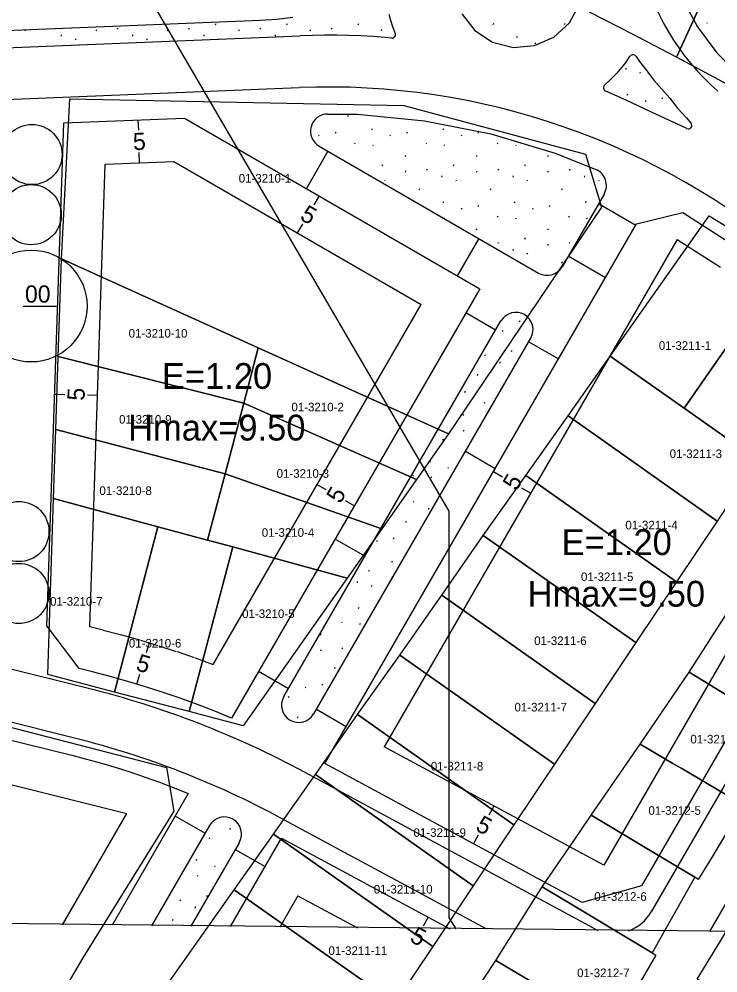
# Model space of a CAD drawing. Extents: x 419396 to 421519, y 4453567 to 4456767.
# Drawn here: x 420843 to 420924.3, y 4454304 to 4454414.9 of the extents above; entities that cross this region are included whole.
import ezdxf

# ---------------------------------------------------------------- set-up
doc = ezdxf.new("R2010")
doc.units = 0
for name, color, linetype in [('0_KADASTRO', 7, 'Continuous'), ('Level 20', 7, 'Continuous'), ('Level 21', 7, 'Continuous'), ('Level 28', 7, 'Continuous'), ('Level 29', 7, 'Continuous'), ('Level 30', 7, 'Continuous'), ('Level 41', 7, 'Continuous'), ('Level 55', 7, 'Continuous'), ('Level 58', 7, 'Continuous'), ('Level 62', 7, 'Continuous'), ('Y_Lejant', 7, 'Continuous')]:
    doc.layers.add(name, color=color, linetype=linetype)

msp = doc.modelspace()

# ---------------------------------------------------------------- linework, layer by layer
at = {"layer": '0_KADASTRO'}
for points in [[(420919.48, 4454410.46), (420927.96, 4454429.01), (420933.84, 4454443.01), (420940.66, 4454439.98), (420932.4, 4454411.65), (420927.17, 4454406.36)], [(420847.97, 4454387.04), (420848.94, 4454405.63), (420887.76, 4454404.85), (420908.91, 4454399.19), (420910.74, 4454393.05), (420892.97, 4454366.7), (420870.84, 4454376.71)], [(420911.76, 4454375.72), (420923.26, 4454392.04), (420932.15, 4454386.63), (420920.36, 4454369.67)], [(420847.59, 4454375.69), (420847.97, 4454387.04), (420870.84, 4454376.71), (420869.17, 4454370.28)], [(420920.36, 4454369.67), (420932.15, 4454386.63), (420932.45, 4454386.45), (420939.89, 4454379.98), (420928.94, 4454363.63)], [(420869.17, 4454370.28), (420870.84, 4454376.71), (420892.97, 4454366.7), (420889.23, 4454361.38)], [(420847.31, 4454367.19), (420847.59, 4454375.69), (420869.17, 4454370.28), (420866.98, 4454362.06)], [(420906.87, 4454368.79), (420911.76, 4454375.72), (420920.36, 4454369.67), (420928.94, 4454363.63), (420924.22, 4454356.56)], [(420866.98, 4454362.06), (420869.17, 4454370.28), (420889.23, 4454361.38), (420885.21, 4454355.65)], [(420901.97, 4454361.84), (420906.87, 4454368.79), (420924.22, 4454356.56), (420919.49, 4454349.5)], [(420847.05, 4454359.2), (420847.31, 4454367.19), (420866.98, 4454362.06), (420864.93, 4454354.34), (420859.18, 4454355.9)], [(420864.93, 4454354.34), (420866.98, 4454362.06), (420885.21, 4454355.65), (420881.19, 4454349.93), (420867.88, 4454353.55)], [(420896.98, 4454354.89), (420901.97, 4454361.84), (420919.49, 4454349.5), (420914.76, 4454342.43)], [(420846.37, 4454338.71), (420847.05, 4454359.2), (420859.18, 4454355.9), (420854.11, 4454336.69)], [(420854.11, 4454336.69), (420859.18, 4454355.9), (420864.93, 4454354.34), (420867.88, 4454353.55), (420862.82, 4454334.41)], [(420892.18, 4454347.94), (420896.98, 4454354.89), (420914.76, 4454342.43), (420910.03, 4454335.37)], [(420920.97, 4454338.99), (420925.86, 4454346.65), (420927.58, 4454349.24), (420931.35, 4454354.92), (420934.95, 4454352.64), (420941.51, 4454348.47), (420936.65, 4454339.79), (420932.18, 4454332.07), (420926.57, 4454335.53), (420923.87, 4454337.2), (420923.23, 4454337.6)], [(420862.82, 4454334.41), (420867.88, 4454353.55), (420881.19, 4454349.93), (420869.1, 4454332.77)], [(420760.42, 4454295.25), (420766.53, 4454352.09), (420860.16, 4454327.91), (420861.03, 4454322.83), (420850.45, 4454305.8), (420831.03, 4454272.79)], [(420887.29, 4454340.99), (420892.18, 4454347.94), (420910.03, 4454335.37), (420905.3, 4454328.31)], [(420882.4, 4454334.06), (420887.29, 4454340.99), (420905.3, 4454328.31), (420900.58, 4454321.24)], [(420915.27, 4454330.63), (420920.97, 4454338.99), (420923.23, 4454337.6), (420923.87, 4454337.2), (420926.57, 4454335.53), (420932.18, 4454332.07), (420927.24, 4454323.56), (420920.1, 4454327.78), (420919.06, 4454328.39)], [(420877.49, 4454327.1), (420882.4, 4454334.06), (420900.58, 4454321.24), (420895.85, 4454314.17)], [(420909.56, 4454322.37), (420915.27, 4454330.63), (420919.06, 4454328.39), (420920.1, 4454327.78), (420927.24, 4454323.56), (420923.49, 4454317.35), (420922.01, 4454314.91), (420921.61, 4454315.15), (420916.01, 4454318.5), (420913.52, 4454320), (420911.58, 4454321.16)], [(420872.6, 4454320.16), (420877.49, 4454327.1), (420895.85, 4454314.17), (420891.13, 4454307.11)], [(420903.86, 4454314.03), (420905.22, 4454316.02), (420908.26, 4454320.46), (420909.56, 4454322.37), (420911.58, 4454321.16), (420913.52, 4454320), (420916.01, 4454318.5), (420921.61, 4454315.15), (420916.66, 4454306.36), (420906.26, 4454312.6)], [(420868.04, 4454313.69), (420872.6, 4454320.16), (420891.13, 4454307.11), (420886.72, 4454300.53)], [(420858.1, 4454299.58), (420868.04, 4454313.69), (420886.72, 4454300.53), (420878.49, 4454288.23)], [(420898.46, 4454305.5), (420903.86, 4454314.03), (420906.26, 4454312.6), (420916.66, 4454306.36), (420917.06, 4454306.11), (420912.04, 4454297.41)], [(420921.9, 4454303.31), (420924.64, 4454307.82), (420926.86, 4454311.47), (420927.5, 4454311.11), (420930.28, 4454309.59), (420939.64, 4454304.45), (420935.53, 4454297.94), (420934.37, 4454296.12), (420930.15, 4454298.55)], [(420887.01, 4454288.07), (420898.46, 4454305.5), (420912.04, 4454297.41), (420906.85, 4454288.65), (420901.63, 4454279.83), (420897.9, 4454281.93), (420892.03, 4454285.24)]]:
    msp.add_lwpolyline(points, close=True, dxfattribs=at)
msp.add_lwpolyline([(420927.96, 4454429.01), (420919.48, 4454410.46), (420914.43, 4454413.1), (420909.36, 4454415.69)], dxfattribs=at)
at = {"layer": 'Level 20'}
for p, q in [((420856.85, 4454403.19), (420856.9, 4454401.99)), ((420857.05, 4454398.19), (420857, 4454399.39)), ((420851.27, 4454344.27), (420853.06, 4454398.03)), ((420853.06, 4454398.03), (420861.04, 4454398.35)), ((420861.04, 4454398.35), (420889.78, 4454381.73)), ((420877.91, 4454394.37), (420877.31, 4454393.33)), ((420875.41, 4454390.04), (420876.01, 4454391.08)), ((420919.56, 4454389.28), (420885.47, 4454330.33)), ((420919.56, 4454389.28), (420924.58, 4454386.06)), ((420865.59, 4454339.89), (420889.78, 4454381.73)), ((420847.17, 4454371.31), (420848.37, 4454371.27)), ((420852.16, 4454371.15), (420850.97, 4454371.19)), ((420940.71, 4454367.94), (420911.01, 4454316.55)), ((420898.19, 4454362.31), (420899.23, 4454361.71)), ((420877.68, 4454360.81), (420878.72, 4454360.21)), ((420902.52, 4454359.8), (420901.48, 4454360.4)), ((420882.01, 4454358.31), (420880.98, 4454358.91)), ((420852.8, 4454343.88), (420851.27, 4454344.27)), ((420852.8, 4454343.88), (420854.94, 4454343.33)), ((420854.94, 4454343.33), (420857.04, 4454342.74)), ((420774.24, 4454342.86), (420855.58, 4454322.58)), ((420857.14, 4454342.71), (420859.18, 4454342.1)), ((420858.16, 4454342.4), (420857.81, 4454341.25)), ((420859.27, 4454342.07), (420861.3, 4454341.41)), ((420861.4, 4454341.38), (420863.41, 4454340.69)), ((420863.5, 4454340.65), (420865.59, 4454339.89)), ((420856.71, 4454337.62), (420857.06, 4454338.76)), ((420911.01, 4454316.55), (420885.47, 4454330.33)), ((420898.24, 4454323.44), (420897.67, 4454322.38)), ((420848.1, 4454309.64), (420855.58, 4454322.58)), ((420895.87, 4454319.04), (420896.44, 4454320.1)), ((420875.46, 4454313.01), (420873.36, 4454309.37)), ((420875.46, 4454313.01), (420882.37, 4454309.28)), ((420890.6, 4454310.52), (420890.03, 4454309.46))]:
    msp.add_line(p, q, dxfattribs=at)
at = {"layer": 'Level 21'}
for p, q in [((420826.86, 4454471.12), (420893.02, 4454357.69)), ((420893.02, 4454357.69), (420893.02, 4454310.43)), ((420893.02, 4454310.43), (420893.8, 4454309.16))]:
    msp.add_line(p, q, dxfattribs=at)
at = {"layer": 'Level 28'}
for p, q in [((420920.13, 4454417.32), (420921.91, 4454414.01)), ((420921.91, 4454414.01), (420924.15, 4454410.99)), ((420924.15, 4454410.99), (420926.81, 4454408.34)), ((420862.28, 4454403.4), (420896.61, 4454383.56)), ((420878.94, 4454403.87), (420882.39, 4454403.85)), ((420882.39, 4454403.85), (420890.18, 4454403.06)), ((420890.18, 4454403.06), (420897.87, 4454401.55)), ((420897.87, 4454401.55), (420905.38, 4454399.32)), ((420877.92, 4454400.14), (420903.44, 4454385.38)), ((420878.95, 4454399.54), (420876.45, 4454395.22)), ((420878.65, 4454399.72), (420880.41, 4454398.7)), ((420905.38, 4454399.32), (420910.08, 4454397.43)), ((420911.07, 4454394.57), (420906.17, 4454386.11)), ((420910.41, 4454393.45), (420914.74, 4454390.94)), ((420914.84, 4454391.12), (420920.21, 4454392.42)), ((420878.57, 4454328.37), (420914.84, 4454391.12)), ((420896.49, 4454389.4), (420893.99, 4454385.07)), ((420906.9, 4454387.37), (420911.23, 4454384.87)), ((420896.61, 4454383.56), (420867.75, 4454333.64)), ((420898.45, 4454378.75), (420894.99, 4454380.75)), ((420901.81, 4454380.55), (420901.81, 4454380.55)), ((420873.82, 4454336.15), (420899.07, 4454379.82)), ((420877.29, 4454334.15), (420902.54, 4454377.82)), ((420902.29, 4454377.4), (420905.76, 4454375.4)), ((420894.93, 4454364.67), (420898.39, 4454362.67)), ((420883.25, 4454352.46), (420879.79, 4454354.46)), ((420874.35, 4454337.07), (420870.89, 4454339.07)), ((420877.6, 4454334.69), (420881.06, 4454332.69)), ((420874.55, 4454333.42), (420874.55, 4454333.42)), ((420862.7, 4454324.91), (420853.84, 4454309.58)), ((420864.64, 4454320.27), (420861.18, 4454322.27)), ((420865.17, 4454321.17), (420858.43, 4454309.53)), ((420867.9, 4454321.91), (420867.9, 4454321.91)), ((420868.63, 4454319.17), (420863.02, 4454309.48)), ((420867.62, 4454309.43), (420873.56, 4454319.71)), ((420868.17, 4454318.39), (420871.64, 4454316.39))]:
    msp.add_line(p, q, dxfattribs=at)
for centre, start, end in [((420878.92, 4454401.87), 89.618, 239.9656), ((420909.33, 4454395.57), 329.9656, 68.1006), ((420904.44, 4454387.12), 239.9656, 329.9656), ((420900.8, 4454378.82), 59.9656, 149.9656), ((420900.8, 4454378.82), 329.9656, 59.9656), ((420875.55, 4454335.15), 149.9656, 239.9656), ((420875.55, 4454335.15), 239.9656, 329.9656), ((420866.9, 4454320.17), 59.9656, 149.9656), ((420866.9, 4454320.17), 329.9656, 59.9656)]:
    msp.add_arc(centre, 2, start, end, dxfattribs=at)
at = {"layer": 'Level 29'}
for p, q in [((420848.22, 4454402.84), (420862.28, 4454403.4)), ((420846.27, 4454344.39), (420848.22, 4454402.84)), ((420920.21, 4454392.42), (420926.2, 4454388.58)), ((420944.38, 4454364.28), (420915.41, 4454314.18)), ((420769.95, 4454349.08), (420849.15, 4454329.33)), ((420850.02, 4454339.42), (420846.27, 4454344.39)), ((420851.57, 4454339.04), (420850.02, 4454339.42)), ((420853.64, 4454338.5), (420851.57, 4454339.04)), ((420855.69, 4454337.92), (420853.64, 4454338.5)), ((420857.73, 4454337.31), (420855.69, 4454337.92)), ((420859.77, 4454336.65), (420857.73, 4454337.31)), ((420861.78, 4454335.96), (420859.77, 4454336.65)), ((420863.79, 4454335.22), (420861.78, 4454335.96)), ((420865.78, 4454334.45), (420863.79, 4454335.22)), ((420867.75, 4454333.64), (420865.78, 4454334.45)), ((420849.15, 4454329.33), (420850.88, 4454328.89)), ((420850.88, 4454328.89), (420852.6, 4454328.41)), ((420852.6, 4454328.41), (420854.31, 4454327.9)), ((420854.31, 4454327.9), (420856.01, 4454327.36)), ((420908.51, 4454312.22), (420878.57, 4454328.37)), ((420856.01, 4454327.36), (420857.7, 4454326.79)), ((420857.7, 4454326.79), (420859.38, 4454326.2)), ((420859.38, 4454326.2), (420861.05, 4454325.57)), ((420861.05, 4454325.57), (420862.7, 4454324.91)), ((420873.56, 4454319.71), (420893.11, 4454309.16)), ((420915.41, 4454314.18), (420908.51, 4454312.22))]:
    msp.add_line(p, q, dxfattribs=at)
at = {"layer": 'Level 41'}
for p, q in [((420865.88, 4454414.25), (420865.95, 4454414.4)), ((420874.17, 4454414.25), (420874.24, 4454414.4)), ((420882.46, 4454414.25), (420882.53, 4454414.4)), ((420898.15, 4454414.28), (420898.23, 4454414.44)), ((420906.45, 4454414.28), (420906.52, 4454414.44)), ((420922.99, 4454414.52), (420923.06, 4454414.41)), ((420843.7, 4454413.52), (420843.77, 4454413.67)), ((420846.22, 4454413.77), (420846.23, 4454413.75)), ((420851.99, 4454413.52), (420852.06, 4454413.68)), ((420854.45, 4454413.86), (420854.53, 4454413.75)), ((420860.28, 4454413.52), (420860.35, 4454413.68)), ((420862.75, 4454413.86), (420862.82, 4454413.75)), ((420868.58, 4454413.52), (420868.65, 4454413.68)), ((420871.04, 4454413.86), (420871.11, 4454413.75)), ((420876.87, 4454413.52), (420876.94, 4454413.68)), ((420879.33, 4454413.86), (420879.4, 4454413.75)), ((420885.16, 4454413.52), (420885.23, 4454413.68)), ((420847.92, 4454413.07), (420847.94, 4454412.91)), ((420849.55, 4454412.6), (420849.62, 4454412.49)), ((420856.21, 4454413.07), (420856.23, 4454412.91)), ((420857.84, 4454412.6), (420857.91, 4454412.49)), ((420864.51, 4454413.07), (420864.52, 4454412.91)), ((420866.14, 4454412.6), (420866.15, 4454412.57)), ((420872.8, 4454413.07), (420872.82, 4454412.91)), ((420881.09, 4454413.07), (420881.1, 4454413)), ((420900.93, 4454412.75), (420901, 4454412.91)), ((420903.02, 4454412.13), (420903.09, 4454412.02)), ((420913.57, 4454409.2), (420913.59, 4454409.04)), ((420915.2, 4454408.73), (420915.27, 4454408.62)), ((420913.74, 4454406.05), (420913.81, 4454406.21)), ((420915.83, 4454405.44), (420915.9, 4454405.33)), ((420917.82, 4454405.64), (420917.89, 4454405.8)), ((420881.27, 4454403.57), (420881.34, 4454403.73)), ((420884.04, 4454402.04), (420884.11, 4454402.2)), ((420892.34, 4454402.04), (420892.41, 4454402.2)), ((420877.84, 4454401.42), (420877.92, 4454401.32)), ((420879.83, 4454401.63), (420879.9, 4454401.79)), ((420886.14, 4454401.42), (420886.21, 4454401.32)), ((420888.13, 4454401.63), (420888.2, 4454401.79)), ((420894.43, 4454401.42), (420894.5, 4454401.32)), ((420896.42, 4454401.63), (420896.49, 4454401.79)), ((420882.05, 4454400.49), (420882.12, 4454400.39)), ((420884.15, 4454400.3), (420884.22, 4454400.2)), ((420890.35, 4454400.49), (420890.42, 4454400.39)), ((420892.44, 4454400.3), (420892.52, 4454400.2)), ((420898.64, 4454400.49), (420898.71, 4454400.39)), ((420900.74, 4454400.3), (420900.81, 4454400.2)), ((420887.89, 4454399.04), (420887.96, 4454398.93)), ((420896.18, 4454399.04), (420896.25, 4454398.93)), ((420904.48, 4454399.04), (420904.55, 4454398.93)), ((420885.25, 4454397.85), (420885.32, 4454398.01)), ((420893.54, 4454397.85), (420893.61, 4454398.01)), ((420901.83, 4454397.85), (420901.91, 4454398.01)), ((420887.95, 4454397.12), (420888.02, 4454397.28)), ((420890.41, 4454397.46), (420890.48, 4454397.36)), ((420892.17, 4454396.67), (420892.19, 4454396.51)), ((420896.24, 4454397.12), (420896.31, 4454397.28)), ((420898.71, 4454397.46), (420898.78, 4454397.36)), ((420900.46, 4454396.67), (420900.48, 4454396.51)), ((420904.53, 4454397.12), (420904.61, 4454397.28)), ((420907, 4454397.46), (420907.07, 4454397.36)), ((420908.76, 4454396.67), (420908.77, 4454396.51)), ((420885.51, 4454396.2), (420885.58, 4454396.1)), ((420893.8, 4454396.2), (420893.87, 4454396.1)), ((420902.09, 4454396.2), (420902.16, 4454396.1)), ((420910.39, 4454396.2), (420910.46, 4454396.1)), ((420889.56, 4454395.06), (420889.64, 4454395.22)), ((420897.86, 4454395.06), (420897.93, 4454395.22)), ((420906.15, 4454395.06), (420906.22, 4454395.22)), ((420892.34, 4454393.53), (420892.41, 4454393.69)), ((420896.42, 4454393.12), (420896.49, 4454393.28)), ((420900.63, 4454393.53), (420900.7, 4454393.69)), ((420904.71, 4454393.12), (420904.78, 4454393.28)), ((420908.92, 4454393.53), (420908.99, 4454393.69)), ((420894.43, 4454392.91), (420894.5, 4454392.81)), ((420902.72, 4454392.91), (420902.79, 4454392.81)), ((420892.44, 4454391.79), (420892.5, 4454391.71)), ((420898.64, 4454391.98), (420898.71, 4454391.88)), ((420900.74, 4454391.79), (420900.81, 4454391.69)), ((420906.93, 4454391.98), (420907, 4454391.88)), ((420909.03, 4454391.79), (420909.1, 4454391.69)), ((420896.18, 4454390.53), (420896.25, 4454390.42)), ((420904.48, 4454390.53), (420904.55, 4454390.42)), ((420898.71, 4454388.95), (420898.78, 4454388.85)), ((420901.83, 4454389.34), (420901.91, 4454389.5)), ((420904.53, 4454388.61), (420904.61, 4454388.77)), ((420907, 4454388.95), (420907.07, 4454388.85)), ((420900.46, 4454388.16), (420900.48, 4454388)), ((420902.09, 4454387.69), (420902.16, 4454387.59)), ((420906.15, 4454386.55), (420906.22, 4454386.71)), ((420901.18, 4454379.82), (420901.25, 4454379.72)), ((420899.2, 4454378.7), (420899.27, 4454378.59)), ((420897.17, 4454375.86), (420897.24, 4454375.76)), ((420900.29, 4454376.25), (420900.37, 4454376.41)), ((420898.92, 4454375.07), (420898.94, 4454374.91)), ((420900.55, 4454374.6), (420900.62, 4454374.5)), ((420896.32, 4454373.46), (420896.39, 4454373.62)), ((420894.88, 4454371.52), (420894.95, 4454371.68)), ((420899.09, 4454371.93), (420899.16, 4454372.09)), ((420897.1, 4454370.38), (420897.17, 4454370.28)), ((420894.64, 4454368.93), (420894.71, 4454368.82)), ((420894.7, 4454367.01), (420894.77, 4454367.17)), ((420892.26, 4454366.09), (420892.33, 4454365.98)), ((420890.8, 4454363.42), (420890.87, 4454363.58)), ((420892.89, 4454362.8), (420892.96, 4454362.7)), ((420888.81, 4454361.87), (420888.88, 4454361.77)), ((420890.9, 4454361.68), (420890.98, 4454361.57)), ((420888.87, 4454358.84), (420888.94, 4454358.74)), ((420890.63, 4454358.05), (420890.65, 4454357.89)), ((420888.02, 4454356.44), (420888.1, 4454356.6)), ((420886.59, 4454354.5), (420886.66, 4454354.66)), ((420884.6, 4454354.29), (420884.67, 4454354.19)), ((420886.35, 4454351.91), (420886.42, 4454351.8)), ((420883.71, 4454350.72), (420883.78, 4454350.88)), ((420886.41, 4454349.99), (420886.48, 4454350.15)), ((420882.34, 4454349.54), (420882.36, 4454349.38)), ((420883.97, 4454349.07), (420884.04, 4454348.96)), ((420882.5, 4454346.4), (420882.57, 4454346.56)), ((420880.51, 4454344.85), (420880.58, 4454344.75)), ((420882.61, 4454344.66), (420882.68, 4454344.55)), ((420878.06, 4454343.4), (420878.13, 4454343.29)), ((420878.11, 4454341.48), (420878.19, 4454341.64)), ((420880.58, 4454341.82), (420880.65, 4454341.72)), ((420879.73, 4454339.42), (420879.8, 4454339.58)), ((420876.3, 4454337.27), (420876.38, 4454337.17)), ((420878.29, 4454337.48), (420878.36, 4454337.64)), ((420874.32, 4454336.15), (420874.39, 4454336.04)), ((420875.42, 4454333.7), (420875.49, 4454333.86)), ((420867.56, 4454320.7), (420867.63, 4454320.86)), ((420865.12, 4454319.78), (420865.19, 4454319.68)), ((420863.65, 4454317.11), (420863.72, 4454317.27)), ((420865.75, 4454316.49), (420865.82, 4454316.39)), ((420863.76, 4454315.37), (420863.83, 4454315.27)), ((420861.73, 4454312.53), (420861.8, 4454312.43)), ((420864.86, 4454312.92), (420864.93, 4454313.08)), ((420863.49, 4454311.74), (420863.51, 4454311.58)), ((420860.88, 4454310.13), (420860.95, 4454310.29))]:
    msp.add_line(p, q, dxfattribs=at)
at = {"layer": 'Level 55'}
for centre in [(420844.53, 4454399.16), (420844.44, 4454392.17), (420843.01, 4454355.34), (420843.01, 4454348.14)]:
    msp.add_circle(centre, 3.5, dxfattribs=at)
at = {"layer": 'Level 58'}
msp.add_line((420843.52, 4454381.55), (420847.36, 4454381.55), dxfattribs=at)
msp.add_circle((420844.44, 4454381.55), 6.5, dxfattribs=at)
at = {"layer": 'Level 62'}
for p, q in [((420907.04, 4454414.48), (420908.21, 4454416.65)), ((420886.04, 4454415.49), (420886.23, 4454414.76)), ((420894.52, 4454415.52), (420896.04, 4454413.57)), ((420728.16, 4454409.01), (420871.12, 4454414.77)), ((420871.12, 4454414.77), (420873, 4454414.9)), ((420873, 4454414.9), (420874.87, 4454415.12)), ((420886.23, 4454414.76), (420886.46, 4454414.04)), ((420905.22, 4454412.81), (420907.04, 4454414.48)), ((420886.46, 4454414.04), (420886.73, 4454413.34)), ((420886.73, 4454413.34), (420886.77, 4454413.23)), ((420896.04, 4454413.57), (420898.1, 4454412.22)), ((420728.14, 4454407.01), (420875.73, 4454412.96)), ((420877.15, 4454413), (420875.73, 4454412.96)), ((420878.56, 4454413.02), (420877.15, 4454413)), ((420879.97, 4454413.02), (420878.56, 4454413.02)), ((420881.38, 4454412.99), (420879.97, 4454413.02)), ((420882.79, 4454412.94), (420881.38, 4454412.99)), ((420884.21, 4454412.87), (420882.79, 4454412.94)), ((420885.61, 4454412.77), (420884.21, 4454412.87)), ((420886.38, 4454412.7), (420885.61, 4454412.77)), ((420898.1, 4454412.22), (420900.5, 4454411.61)), ((420902.96, 4454411.82), (420905.22, 4454412.81)), ((420900.5, 4454411.61), (420902.96, 4454411.82)), ((420913.17, 4454409.33), (420913.61, 4454409.91)), ((420913.61, 4454409.91), (420914.02, 4454410.5)), ((420914.02, 4454410.5), (420914.04, 4454410.54)), ((420914.8, 4454410.55), (420915.19, 4454409.98)), ((420915.19, 4454409.98), (420916.01, 4454408.87)), ((420912.2, 4454408.25), (420912.7, 4454408.78)), ((420912.7, 4454408.78), (420913.17, 4454409.33)), ((420916.01, 4454408.87), (420916.86, 4454407.79)), ((420911.14, 4454407.27), (420911.68, 4454407.75)), ((420911.68, 4454407.75), (420912.2, 4454408.25)), ((420916.86, 4454407.79), (420917.76, 4454406.74)), ((420745, 4454401.68), (420875.59, 4454406.95)), ((420913.64, 4454405.48), (420911.26, 4454406.51)), ((420917.76, 4454406.74), (420918.69, 4454405.72)), ((420916.64, 4454404.04), (420913.64, 4454405.48)), ((420918.69, 4454405.72), (420919.61, 4454404.54)), ((420919.61, 4454404.54), (420920.64, 4454403.41)), ((420920.11, 4454402.45), (420916.64, 4454404.04)), ((420920.64, 4454403.41), (420921.16, 4454402.8)), ((420920.68, 4454402.18), (420920.11, 4454402.45)), ((420851.09, 4454337.1), (420741.02, 4454364.54)), ((420946.1, 4454362.27), (420916.54, 4454311.13)), ((420849.64, 4454331.28), (420741.69, 4454358.19)), ((420950.95, 4454356.67), (420923.3, 4454308.85)), ((420909.83, 4454309.24), (420876.23, 4454327.36)), ((420897.41, 4454309.12), (420873.39, 4454322.08))]:
    msp.add_line(p, q, dxfattribs=at)
for centre, radius, start, end in [((420942.28, 4454427.43), 27.57, 155.3866, 229.2728), ((420886.42, 4454413.08), 0.384, 264.992, 23.1766), ((420914.43, 4454410.3), 0.451, 34.4308, 147.7062), ((420878.95, 4454323.48), 83.53, 49.2728, 92.3077), ((420911.44, 4454406.93), 0.452, 131.6363, 246.5338), ((420920.86, 4454402.54), 0.403, 244.44, 40.5251), ((420824.96, 4454232.31), 108, 61.6578, 76.002), ((420824.96, 4454232.31), 102, 61.6578, 76.002), ((420912.21, 4454313.64), 5, 290.2564, 329.9656), ((420912.21, 4454313.64), 5, 241.6578, 248.545)]:
    msp.add_arc(centre, radius, start, end, dxfattribs=at)
at = {"layer": 'Y_Lejant'}
msp.add_lwpolyline([(420209.76, 4455704.6), (421518.56, 4455690.86), (421518.56, 4454302.65), (420195.09, 4454316.54)], close=True, dxfattribs=at)

# ---------------------------------------------------------------- texts
at = {"layer": '0_KADASTRO'}
for s, p in [('01-3210-1', (420868.57, 4454395.9)), ('01-3210-10', (420855.77, 4454377.88)), ('01-3211-1', (420917.42, 4454376.46)), ('01-3210-2', (420874.7, 4454369.31)), ('01-3210-9', (420854.66, 4454367.88)), ('01-3211-3', (420918.68, 4454363.88)), ('01-3210-3', (420872.98, 4454361.59)), ('01-3210-8', (420852.37, 4454359.59)), ('01-3210-4', (420871.26, 4454354.73)), ('01-3211-4', (420913.53, 4454355.59)), ('01-3211-5', (420908.37, 4454349.58)), ('01-3210-7', (420846.64, 4454346.72)), ('01-3210-5', (420868.97, 4454345.29)), ('01-3210-6', (420855.8, 4454341.86)), ('01-3211-6', (420902.93, 4454342.15)), ('01-3211-7', (420900.64, 4454334.43)), ('01-3212-4', (420921.09, 4454330.71)), ('01-3211-8', (420890.91, 4454327.57)), ('01-3212-5', (420916.22, 4454322.42)), ('01-3211-9', (420888.9, 4454319.85)), ('01-3211-10', (420884.28, 4454313.27)), ('01-3212-6', (420909.92, 4454312.42)), ('01-3211-11', (420879.01, 4454306.13)), ('01-3212-7', (420907.92, 4454303.55))]:
    msp.add_text(s, height=1, dxfattribs=at).set_placement(p)
at = {"layer": 'Level 20'}
for rotation, p in [(2.3077, (420856.32, 4454399.66)), (329.9656, (420875.58, 4454391.67)), (88.0908, (420850.64, 4454370.53)), (59.9656, (420900.88, 4454359.98)), (59.9656, (420880.38, 4454358.48)), (343.2227, (420856.51, 4454339.25)), (331.6578, (420895.99, 4454320.68)), (331.6578, (420888.35, 4454307.76))]:
    msp.add_text('5', height=2, rotation=rotation, dxfattribs=at).set_placement(p)
at = {"layer": 'Level 30'}
for s, p in [('E=1.20', (420859.64, 4454371.92)), ('Hmax=9.50', (420855.71, 4454365.92)), ('E=1.20', (420906.11, 4454352.61)), ('Hmax=9.50', (420902.17, 4454346.61))]:
    msp.add_text(s, height=3, dxfattribs=at).set_placement(p)
at = {"layer": 'Level 58'}
msp.add_text('00', height=1.998, dxfattribs=at).set_placement((420843.72, 4454381.95))

doc.saveas('drawing.dxf')
